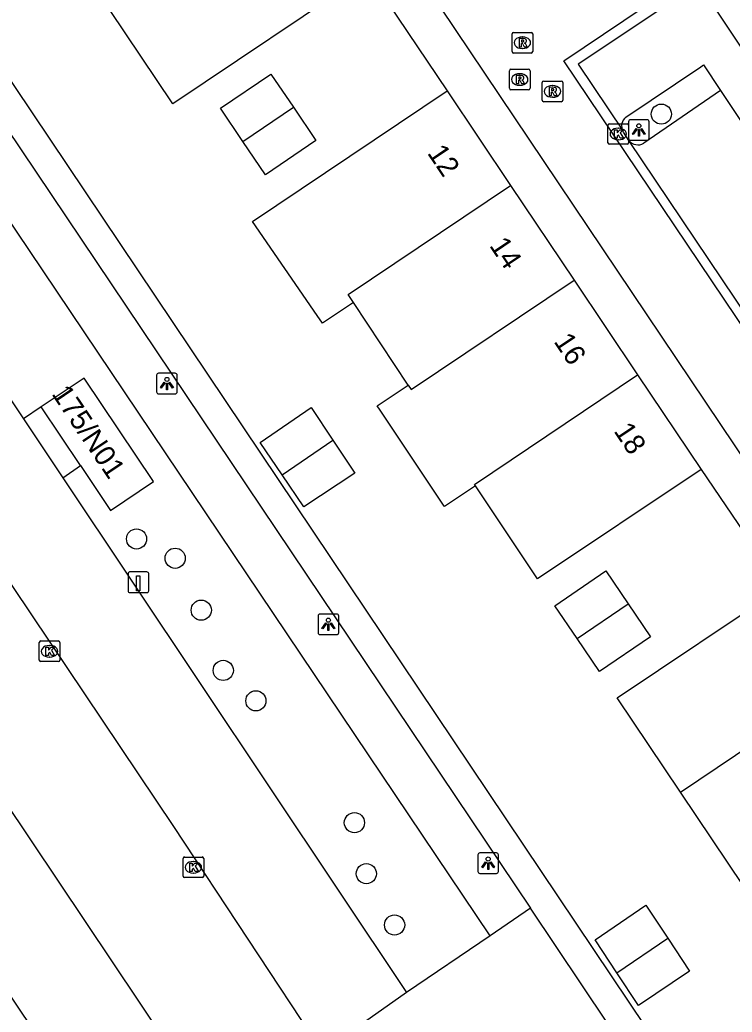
# Model space of a CAD drawing. Extents: x 158797 to 159887, y 384318 to 385255.
# Drawn here: x 159107.09 to 159141.62, y 384481.11 to 384529.23 of the extents above; entities that cross this region are included whole.
import ezdxf

# ---------------------------------------------------------------- set-up
doc = ezdxf.new("R2010")
doc.units = 0
for name, color, linetype in [('IMGEO_Boom', 7, 'Continuous'), ('IMGEO_Groenvoorziening', 7, 'Continuous'), ('IMGEO_Kolk', 7, 'Continuous'), ('IMGEO_Laadpaal', 7, 'Continuous'), ('IMGEO_Lichtpunt', 7, 'Continuous'), ('IMGEO_Pand', 7, 'Continuous'), ('IMGEO_Pand_nummerreeks', 7, 'Continuous'), ('IMGEO_Parkeervlak_open', 7, 'Continuous'), ('IMGEO_Rijbaan_lokaal_open', 7, 'Continuous'), ('IMGEO_Rioolput', 7, 'Continuous'), ('IMGEO_Voetpad_open', 7, 'Continuous')]:
    doc.layers.add(name, color=color, linetype=linetype)

msp = doc.modelspace()

# ---------------------------------------------------------------- linework, layer by layer
at = {"layer": 'IMGEO_Boom'}
for centre in [(159138.19, 384524.66), (159112.752, 384504.056), (159114.623, 384503.12), (159115.887, 384500.603), (159116.955, 384497.682), (159118.536, 384496.206), (159123.312, 384490.297), (159123.889, 384487.824), (159125.259, 384485.335)]:
    msp.add_circle(centre, 0.489, dxfattribs=at)
at = {"layer": 'IMGEO_Groenvoorziening'}
msp.add_lwpolyline([(159129.89, 384484.816), (159089.196, 384545.377)], dxfattribs=at)
at = {"layer": 'IMGEO_Kolk'}
for p, q in [((159135.603, 384523.27), (159135.603, 384524.122)), ((159135.678, 384524.196), (159136.53, 384524.196)), ((159136.604, 384524.122), (159136.604, 384523.27)), ((159136.091, 384523.976), (159136.116, 384523.976)), ((159136.53, 384523.196), (159135.678, 384523.196)), ((159136.114, 384523.416), (159136.089, 384523.416)), ((159108.107, 384499.108), (159108.959, 384499.108)), ((159108.032, 384498.182), (159108.032, 384499.034)), ((159108.52, 384498.888), (159108.545, 384498.888)), ((159109.033, 384499.034), (159109.033, 384498.182)), ((159108.543, 384498.328), (159108.518, 384498.328)), ((159108.959, 384498.108), (159108.107, 384498.108)), ((159115.005, 384487.706), (159115.005, 384488.558)), ((159115.08, 384488.632), (159115.932, 384488.632)), ((159116.006, 384488.558), (159116.006, 384487.706)), ((159115.493, 384488.412), (159115.518, 384488.412)), ((159115.932, 384487.632), (159115.08, 384487.632)), ((159115.516, 384487.852), (159115.491, 384487.852))]:
    msp.add_line(p, q, dxfattribs=at)
for points in [[(159135.603, 384523.27), (159135.603, 384524.122)], [(159135.678, 384524.196), (159136.53, 384524.196)], [(159136.604, 384524.122), (159136.604, 384523.27)], [(159135.924, 384523.896), (159136.047, 384523.896), (159136.047, 384523.745), (159136.177, 384523.896), (159136.341, 384523.896), (159136.195, 384523.745), (159136.348, 384523.496), (159136.196, 384523.496), (159136.111, 384523.66), (159136.047, 384523.593), (159136.047, 384523.496), (159135.924, 384523.496), (159135.924, 384523.896)], [(159136.53, 384523.196), (159135.678, 384523.196)], [(159108.107, 384499.108), (159108.959, 384499.108)], [(159108.032, 384498.182), (159108.032, 384499.034)], [(159108.353, 384498.808), (159108.476, 384498.808), (159108.476, 384498.657), (159108.606, 384498.808), (159108.77, 384498.808), (159108.624, 384498.657), (159108.777, 384498.408), (159108.625, 384498.408), (159108.54, 384498.572), (159108.476, 384498.505), (159108.476, 384498.408), (159108.353, 384498.408), (159108.353, 384498.808)], [(159109.033, 384499.034), (159109.033, 384498.182)], [(159108.959, 384498.108), (159108.107, 384498.108)], [(159115.005, 384487.706), (159115.005, 384488.558)], [(159115.08, 384488.632), (159115.932, 384488.632)], [(159116.006, 384488.558), (159116.006, 384487.706)], [(159115.326, 384488.332), (159115.449, 384488.332), (159115.449, 384488.181), (159115.579, 384488.332), (159115.743, 384488.332), (159115.597, 384488.181), (159115.75, 384487.932), (159115.598, 384487.932), (159115.513, 384488.096), (159115.449, 384488.029), (159115.449, 384487.932), (159115.326, 384487.932), (159115.326, 384488.332)], [(159115.932, 384487.632), (159115.08, 384487.632)]]:
    msp.add_lwpolyline(points, dxfattribs=at)
for centre, start, end in [((159135.68, 384524.12), 91.552, 178.448), ((159135.68, 384524.12), 91.552, 178.448), ((159136.528, 384524.12), 1.552, 88.448), ((159136.528, 384524.12), 1.552, 88.448), ((159135.68, 384523.272), 181.552, 268.448), ((159135.68, 384523.272), 181.552, 268.448), ((159136.528, 384523.272), 271.552, 358.448), ((159136.528, 384523.272), 271.552, 358.448), ((159108.109, 384499.032), 91.552, 178.448), ((159108.109, 384499.032), 91.552, 178.448), ((159108.957, 384499.032), 1.552, 88.448), ((159108.957, 384499.032), 1.552, 88.448), ((159108.109, 384498.184), 181.552, 268.448), ((159108.109, 384498.184), 181.552, 268.448), ((159108.957, 384498.184), 271.552, 358.448), ((159108.957, 384498.184), 271.552, 358.448), ((159115.082, 384488.556), 91.552, 178.448), ((159115.082, 384488.556), 91.552, 178.448), ((159115.93, 384488.556), 1.552, 88.448), ((159115.93, 384488.556), 1.552, 88.448), ((159115.082, 384487.708), 181.552, 268.448), ((159115.082, 384487.708), 181.552, 268.448), ((159115.93, 384487.708), 271.552, 358.448), ((159115.93, 384487.708), 271.552, 358.448)]:
    msp.add_arc(centre, 0.0765, start, end, dxfattribs=at)
for centre, major_axis, ratio, start_param, end_param in [((159136.09, 384523.696), (-0.387, 0.002), 0.722429, 4.712389, 7.853982), ((159136.115, 384523.696), (-0.39, 0.002), 0.717154, 1.570796, 4.712389), ((159108.519, 384498.608), (-0.387, 0.002), 0.722429, 4.712389, 7.853982), ((159108.544, 384498.608), (-0.39, 0.002), 0.717154, 1.570796, 4.712389), ((159115.492, 384488.132), (-0.387, 0.002), 0.722429, 4.712389, 7.853982), ((159115.517, 384488.132), (-0.39, 0.002), 0.717154, 1.570796, 4.712389)]:
    msp.add_ellipse(centre, major_axis=major_axis, ratio=ratio, start_param=start_param, end_param=end_param, dxfattribs=at)
at = {"layer": 'IMGEO_Laadpaal'}
for p, q in [((159113.257, 384502.457), (159112.416, 384502.457)), ((159113.257, 384502.457), (159112.416, 384502.457)), ((159112.341, 384502.373), (159112.341, 384501.532)), ((159112.341, 384502.373), (159112.341, 384501.532)), ((159113.341, 384501.541), (159113.341, 384502.382)), ((159113.341, 384501.541), (159113.341, 384502.382)), ((159112.425, 384501.457), (159113.266, 384501.457)), ((159112.425, 384501.457), (159113.266, 384501.457))]:
    msp.add_line(p, q, dxfattribs=at)
msp.add_lwpolyline([(159112.756, 384502.27), (159112.916, 384502.27), (159112.916, 384501.537), (159112.756, 384501.537), (159112.756, 384502.27)], dxfattribs=at)
for centre, start, end in [((159112.419, 384502.379), 92.4484, 184.2845), ((159112.419, 384502.379), 92.4484, 184.2845), ((159113.263, 384502.379), 2.4484, 94.2845), ((159113.263, 384502.379), 2.4484, 94.2845), ((159112.419, 384501.535), 182.4484, 274.2845), ((159112.419, 384501.535), 182.4484, 274.2845), ((159113.263, 384501.535), 272.4484, 4.2845), ((159113.263, 384501.535), 272.4484, 4.2845)]:
    msp.add_arc(centre, 0.0779, start, end, dxfattribs=at)
at = {"layer": 'IMGEO_Lichtpunt'}
for p, q in [((159136.602, 384524.293), (159136.602, 384523.486)), ((159136.602, 384524.293), (159136.602, 384523.486)), ((159137.504, 384524.388), (159136.696, 384524.388)), ((159137.504, 384524.388), (159136.696, 384524.388)), ((159137.598, 384523.486), (159137.598, 384524.293)), ((159137.598, 384523.486), (159137.598, 384524.293)), ((159136.696, 384523.392), (159137.504, 384523.392)), ((159136.696, 384523.392), (159137.504, 384523.392)), ((159114.625, 384512.091), (159113.817, 384512.091)), ((159114.625, 384512.091), (159113.817, 384512.091)), ((159113.723, 384511.996), (159113.723, 384511.189)), ((159113.723, 384511.996), (159113.723, 384511.189)), ((159114.719, 384511.189), (159114.719, 384511.996)), ((159114.719, 384511.189), (159114.719, 384511.996)), ((159113.817, 384511.095), (159114.625, 384511.095)), ((159113.817, 384511.095), (159114.625, 384511.095)), ((159121.553, 384500.319), (159121.553, 384499.512)), ((159121.553, 384500.319), (159121.553, 384499.512)), ((159122.455, 384500.414), (159121.647, 384500.414)), ((159122.455, 384500.414), (159121.647, 384500.414)), ((159122.549, 384499.512), (159122.549, 384500.319)), ((159122.549, 384499.512), (159122.549, 384500.319)), ((159121.647, 384499.418), (159122.455, 384499.418)), ((159121.647, 384499.418), (159122.455, 384499.418)), ((159129.297, 384488.738), (159129.297, 384487.931)), ((159129.297, 384488.738), (159129.297, 384487.931)), ((159130.199, 384488.833), (159129.391, 384488.833)), ((159130.199, 384488.833), (159129.391, 384488.833)), ((159130.293, 384487.931), (159130.293, 384488.738)), ((159130.293, 384487.931), (159130.293, 384488.738)), ((159129.391, 384487.837), (159130.199, 384487.837)), ((159129.391, 384487.837), (159130.199, 384487.837))]:
    msp.add_line(p, q, dxfattribs=at)
for points in [[(159136.976, 384523.957), (159137.015, 384523.929), (159136.827, 384523.667), (159136.789, 384523.694), (159136.976, 384523.957)], [(159137.078, 384523.909), (159137.125, 384523.909), (159137.125, 384523.587), (159137.078, 384523.587), (159137.078, 384523.909)], [(159137.188, 384523.929), (159137.226, 384523.956), (159137.413, 384523.694), (159137.374, 384523.666), (159137.188, 384523.929)], [(159114.097, 384511.66), (159114.136, 384511.632), (159113.948, 384511.37), (159113.91, 384511.397), (159114.097, 384511.66)], [(159114.199, 384511.612), (159114.246, 384511.612), (159114.246, 384511.29), (159114.199, 384511.29), (159114.199, 384511.612)], [(159114.309, 384511.632), (159114.347, 384511.659), (159114.534, 384511.397), (159114.495, 384511.369), (159114.309, 384511.632)], [(159121.927, 384499.983), (159121.966, 384499.955), (159121.778, 384499.693), (159121.74, 384499.72), (159121.927, 384499.983)], [(159122.029, 384499.935), (159122.076, 384499.935), (159122.076, 384499.613), (159122.029, 384499.613), (159122.029, 384499.935)], [(159122.139, 384499.955), (159122.177, 384499.982), (159122.364, 384499.72), (159122.325, 384499.692), (159122.139, 384499.955)], [(159129.671, 384488.402), (159129.71, 384488.374), (159129.522, 384488.112), (159129.484, 384488.139), (159129.671, 384488.402)], [(159129.773, 384488.354), (159129.82, 384488.354), (159129.82, 384488.032), (159129.773, 384488.032), (159129.773, 384488.354)], [(159129.883, 384488.374), (159129.921, 384488.401), (159130.108, 384488.139), (159130.069, 384488.111), (159129.883, 384488.374)]]:
    msp.add_lwpolyline(points, dxfattribs=at)
for centre in [(159137.101, 384524.091), (159114.222, 384511.794), (159122.052, 384500.117), (159129.796, 384488.536)]:
    msp.add_circle(centre, 0.0994, dxfattribs=at)
for centre, start, end in [((159136.696, 384524.293), 90, 180), ((159136.696, 384524.293), 90, 180), ((159137.504, 384524.293), 0, 90), ((159137.504, 384524.293), 0, 90), ((159136.696, 384523.486), 180, 270), ((159136.696, 384523.486), 180, 270), ((159137.504, 384523.486), 270, 0), ((159137.504, 384523.486), 270, 360), ((159113.817, 384511.996), 90, 180), ((159113.817, 384511.996), 90, 180), ((159114.625, 384511.996), 0, 90), ((159114.625, 384511.996), 0, 90), ((159113.817, 384511.189), 180, 270), ((159113.817, 384511.189), 180, 270), ((159114.625, 384511.189), 270, 0), ((159114.625, 384511.189), 270, 360), ((159121.647, 384500.319), 90, 180), ((159121.647, 384500.319), 90, 180), ((159122.455, 384500.319), 0, 90), ((159122.455, 384500.319), 0, 90), ((159121.647, 384499.512), 180, 270), ((159121.647, 384499.512), 180, 270), ((159122.455, 384499.512), 270, 0), ((159122.455, 384499.512), 270, 360), ((159129.391, 384488.738), 90, 180), ((159129.391, 384488.738), 90, 180), ((159130.199, 384488.738), 0, 90), ((159130.199, 384488.738), 0, 90), ((159129.391, 384487.931), 180, 270), ((159129.391, 384487.931), 180, 270), ((159130.199, 384487.931), 270, 0), ((159130.199, 384487.931), 270, 360)]:
    msp.add_arc(centre, 0.0946, start, end, dxfattribs=at)
at = {"layer": 'IMGEO_Pand'}
for points in [[(159126.029, 384461.936), (159121.905, 384459.166), (159071.774, 384533.799)], [(159123.956, 384531.511), (159114.509, 384525.165), (159111.442, 384529.73), (159111.219, 384530.062), (159112.722, 384531.071)], [(159117.91, 384523.327), (159116.822, 384524.941), (159119.268, 384526.601), (159120.354, 384524.991)], [(159123.26, 384515.516), (159121.762, 384514.518), (159121.501, 384514.897), (159118.368, 384519.453), (159127.802, 384525.792)], [(159127.802, 384525.792), (159130.881, 384521.199)], [(159120.354, 384524.991), (159121.441, 384523.38), (159118.994, 384521.72), (159117.91, 384523.327)], [(159117.91, 384523.327), (159120.354, 384524.991)], [(159123.26, 384515.516), (159123.001, 384515.905), (159130.881, 384521.199)], [(159130.881, 384521.199), (159133.961, 384516.607)], [(159125.922, 384511.522), (159126.067, 384511.304), (159133.961, 384516.607)], [(159133.961, 384516.607), (159137.04, 384512.015)], [(159125.922, 384511.522), (159123.26, 384515.516)], [(159110.027, 384507.615), (159111.49, 384505.432), (159113.576, 384506.843), (159110.211, 384511.86), (159108.122, 384510.457)], [(159129.183, 384506.629), (159129.133, 384506.703), (159137.04, 384512.015)], [(159137.04, 384512.015), (159140.119, 384507.423)], [(159129.183, 384506.629), (159127.677, 384505.625), (159127.631, 384505.694), (159124.565, 384510.295), (159124.416, 384510.518), (159125.922, 384511.522)], [(159110.027, 384507.615), (159108.122, 384510.457)], [(159119.812, 384507.166), (159118.745, 384508.741), (159121.221, 384510.427), (159122.273, 384508.841)], [(159122.273, 384508.841), (159123.325, 384507.255), (159120.863, 384505.615), (159119.812, 384507.166)], [(159119.812, 384507.166), (159122.273, 384508.841)], [(159140.119, 384507.423), (159132.189, 384502.119), (159129.183, 384506.629)], [(159134.111, 384499.224), (159133.034, 384500.821), (159135.504, 384502.503), (159136.581, 384500.905)], [(159139.121, 384491.775), (159136.05, 384496.35), (159144.008, 384501.688)], [(159136.581, 384500.905), (159137.658, 384499.307), (159135.188, 384497.625), (159134.111, 384499.224)], [(159134.111, 384499.224), (159136.581, 384500.905)], [(159139.121, 384491.775), (159147.07, 384497.12)], [(159142.186, 384487.209), (159139.121, 384491.775)], [(159136.036, 384483.019), (159134.977, 384484.616), (159137.439, 384486.292), (159138.5, 384484.696)], [(159138.5, 384484.696), (159139.56, 384483.1), (159137.088, 384481.434), (159136.036, 384483.019)], [(159136.036, 384483.019), (159138.5, 384484.696)]]:
    msp.add_lwpolyline(points, dxfattribs=at)
at = {"layer": 'IMGEO_Parkeervlak_open'}
for points in [[(159085.318, 384542.737), (159107.263, 384509.883)], [(159141.058, 384525.803), (159137.334, 384523.246)], [(159109.176, 384507.019), (159125.843, 384482.068)]]:
    msp.add_lwpolyline(points, dxfattribs=at)
msp.add_arc((159137.049, 384523.731), 0.562, 218.3312, 300.4486, dxfattribs=at)
at = {"layer": 'IMGEO_Rijbaan_lokaal_open'}
for points in [[(159108.917, 384557.49), (159163.183, 384476.655)], [(159190.205, 384527.153), (159192.762, 384528.848), (159193.039, 384528.419), (159151.428, 384500.515), (159133.468, 384527.238), (159175.064, 384555.242), (159175.35, 384554.823), (159172.804, 384553.09)], [(159125.843, 384482.068), (159121.763, 384479.19), (159114.556, 384490.118), (159081.78, 384538.994), (159081.166, 384539.91)], [(159076.06, 384536.619), (159126.029, 384461.936)], [(159140.006, 384531.001), (159134.158, 384527.09), (159136.335, 384523.829)], [(159136.608, 384523.382), (159136.361, 384523.789), (159136.347, 384523.809), (159136.335, 384523.829)], [(159143.075, 384513.765), (159136.608, 384523.382)], [(159131.847, 384486.145), (159129.89, 384484.816)], [(159146.803, 384466.42), (159146.046, 384465.91), (159145.592, 384465.604), (159131.847, 384486.145)], [(159129.89, 384484.816), (159125.843, 384482.068)]]:
    msp.add_lwpolyline(points, dxfattribs=at)
at = {"layer": 'IMGEO_Rioolput'}
for p, q in [((159130.953, 384527.697), (159130.953, 384528.549)), ((159131.028, 384528.623), (159131.88, 384528.623)), ((159131.954, 384528.549), (159131.954, 384527.697)), ((159131.441, 384528.403), (159131.466, 384528.403)), ((159131.88, 384527.623), (159131.028, 384527.623)), ((159131.464, 384527.843), (159131.439, 384527.843)), ((159130.823, 384525.912), (159130.823, 384526.764)), ((159130.898, 384526.838), (159131.75, 384526.838)), ((159131.311, 384526.618), (159131.336, 384526.618)), ((159131.824, 384526.764), (159131.824, 384525.912)), ((159131.334, 384526.058), (159131.309, 384526.058)), ((159132.412, 384525.334), (159132.412, 384526.186)), ((159132.487, 384526.26), (159133.339, 384526.26)), ((159132.9, 384526.04), (159132.925, 384526.04)), ((159133.413, 384526.186), (159133.413, 384525.334)), ((159131.75, 384525.838), (159130.898, 384525.838)), ((159133.339, 384525.26), (159132.487, 384525.26)), ((159132.923, 384525.48), (159132.898, 384525.48))]:
    msp.add_line(p, q, dxfattribs=at)
for points in [[(159130.953, 384527.697), (159130.953, 384528.549)], [(159131.028, 384528.623), (159131.88, 384528.623)], [(159131.954, 384528.549), (159131.954, 384527.697)], [(159131.542, 384528.321), (159131.29, 384528.323), (159131.29, 384527.923)], [(159131.29, 384527.923), (159131.414, 384527.923), (159131.414, 384528.085), (159131.425, 384528.085)], [(159131.468, 384528.242), (159131.414, 384528.242), (159131.414, 384528.161)], [(159131.414, 384528.161), (159131.466, 384528.161)], [(159131.472, 384528.056), (159131.543, 384527.923), (159131.683, 384527.923), (159131.618, 384528.049)], [(159131.88, 384527.623), (159131.028, 384527.623)], [(159130.823, 384525.912), (159130.823, 384526.764)], [(159130.898, 384526.838), (159131.75, 384526.838)], [(159131.412, 384526.536), (159131.16, 384526.538), (159131.16, 384526.138)], [(159131.824, 384526.764), (159131.824, 384525.912)], [(159131.16, 384526.138), (159131.284, 384526.138), (159131.284, 384526.3), (159131.295, 384526.3)], [(159131.338, 384526.457), (159131.284, 384526.457), (159131.284, 384526.376)], [(159131.284, 384526.376), (159131.336, 384526.376)], [(159131.342, 384526.271), (159131.413, 384526.138), (159131.553, 384526.138), (159131.488, 384526.264)], [(159132.412, 384525.334), (159132.412, 384526.186)], [(159132.487, 384526.26), (159133.339, 384526.26)], [(159133.413, 384526.186), (159133.413, 384525.334)], [(159131.75, 384525.838), (159130.898, 384525.838)], [(159133.001, 384525.958), (159132.749, 384525.96), (159132.749, 384525.56)], [(159132.749, 384525.56), (159132.873, 384525.56), (159132.873, 384525.722), (159132.884, 384525.722)], [(159132.927, 384525.879), (159132.873, 384525.879), (159132.873, 384525.798)], [(159132.873, 384525.798), (159132.925, 384525.798)], [(159132.931, 384525.693), (159133.002, 384525.56), (159133.142, 384525.56), (159133.077, 384525.686)], [(159133.339, 384525.26), (159132.487, 384525.26)]]:
    msp.add_lwpolyline(points, dxfattribs=at)
for centre, radius, start, end in [((159131.03, 384528.547), 0.0765, 91.552, 178.448), ((159131.03, 384528.547), 0.0765, 91.552, 178.448), ((159131.878, 384528.547), 0.0765, 1.552, 88.448), ((159131.878, 384528.547), 0.0765, 1.552, 88.448), ((159131.424, 384528.032), 0.0533, 26.0293, 88.6989), ((159131.45, 384528.35), 0.19, 274.7715, 282.9687), ((159131.474, 384528.146), 0.0964, 77.0061, 93.1865), ((159131.488, 384528.203), 0.0378, 276.6634, 79.6772), ((159131.541, 384528.211), 0.109, 350.3612, 89.416), ((159131.539, 384528.211), 0.112, 277.5842, 350.9817), ((159131.523, 384527.996), 0.108, 29.5134, 73.7905), ((159131.03, 384527.699), 0.0765, 181.552, 268.448), ((159131.03, 384527.699), 0.0765, 181.552, 268.448), ((159131.878, 384527.699), 0.0765, 271.552, 358.448), ((159131.878, 384527.699), 0.0765, 271.552, 358.448), ((159130.9, 384526.762), 0.0765, 91.552, 178.448), ((159130.9, 384526.762), 0.0765, 91.552, 178.448), ((159131.411, 384526.426), 0.109, 350.3612, 89.416), ((159131.748, 384526.762), 0.0765, 1.552, 88.448), ((159131.748, 384526.762), 0.0765, 1.552, 88.448), ((159131.294, 384526.247), 0.0533, 26.0293, 88.6989), ((159131.32, 384526.565), 0.19, 274.7715, 282.9687), ((159131.344, 384526.361), 0.0964, 77.0061, 93.1865), ((159131.358, 384526.418), 0.0378, 276.6634, 79.6772), ((159131.409, 384526.426), 0.112, 277.5842, 350.9817), ((159131.393, 384526.211), 0.108, 29.5134, 73.7905), ((159132.489, 384526.184), 0.0765, 91.552, 178.448), ((159132.489, 384526.184), 0.0765, 91.552, 178.448), ((159133.337, 384526.184), 0.0765, 1.552, 88.448), ((159133.337, 384526.184), 0.0765, 1.552, 88.448), ((159130.9, 384525.914), 0.0765, 181.552, 268.448), ((159130.9, 384525.914), 0.0765, 181.552, 268.448), ((159131.748, 384525.914), 0.0765, 271.552, 358.448), ((159131.748, 384525.914), 0.0765, 271.552, 358.448), ((159132.883, 384525.669), 0.0533, 26.0293, 88.6989), ((159132.909, 384525.987), 0.19, 274.7715, 282.9687), ((159132.933, 384525.783), 0.0964, 77.0061, 93.1865), ((159132.947, 384525.84), 0.0378, 276.6634, 79.6772), ((159133, 384525.848), 0.109, 350.3612, 89.416), ((159132.998, 384525.848), 0.112, 277.5842, 350.9817), ((159132.982, 384525.633), 0.108, 29.5134, 73.7905), ((159132.489, 384525.336), 0.0765, 181.552, 268.448), ((159132.489, 384525.336), 0.0765, 181.552, 268.448), ((159133.337, 384525.336), 0.0765, 271.552, 358.448), ((159133.337, 384525.336), 0.0765, 271.552, 358.448)]:
    msp.add_arc(centre, radius, start, end, dxfattribs=at)
for centre, major_axis, ratio, start_param, end_param in [((159131.44, 384528.123), (-0.387, 0.002), 0.722429, 4.712389, 7.853982), ((159131.465, 384528.123), (-0.39, 0.002), 0.717154, 1.570796, 4.712389), ((159131.31, 384526.338), (-0.387, 0.002), 0.722429, 4.712389, 7.853982), ((159131.335, 384526.338), (-0.39, 0.002), 0.717154, 1.570796, 4.712389), ((159132.899, 384525.76), (-0.387, 0.002), 0.722429, 4.712389, 7.853982), ((159132.924, 384525.76), (-0.39, 0.002), 0.717154, 1.570796, 4.712389)]:
    msp.add_ellipse(centre, major_axis=major_axis, ratio=ratio, start_param=start_param, end_param=end_param, dxfattribs=at)
at = {"layer": 'IMGEO_Voetpad_open'}
for points in [[(159146.803, 384466.42), (159092.403, 384547.537), (159106.711, 384557.186), (159108.605, 384554.36)], [(159089.196, 384545.377), (159091.171, 384546.721), (159131.847, 384486.145)], [(159123.956, 384531.511), (159127.802, 384525.792)], [(159143.371, 384525.955), (159140.006, 384531.001)], [(159136.474, 384524.51), (159140.1, 384526.959), (159140.226, 384527.044), (159141.058, 384525.803)], [(159141.058, 384525.803), (159146.94, 384516.973)], [(159108.122, 384510.457), (159107.263, 384509.883)], [(159107.263, 384509.883), (159109.176, 384507.019)], [(159109.176, 384507.019), (159110.027, 384507.615)], [(159140.119, 384507.423), (159144.008, 384501.688)]]:
    msp.add_lwpolyline(points, dxfattribs=at)
msp.add_arc((159136.78, 384524.093), 0.518, 126.2904, 210.6371, dxfattribs=at)

# ---------------------------------------------------------------- texts
at = {"layer": 'IMGEO_Pand_nummerreeks'}
for s, rotation, p in [('12', 303.8387, (159126.817, 384522.772)), ('14', 303.8501, (159129.828, 384518.283)), ('16', 303.8444, (159132.945, 384513.634)), ('175/N01', 303.8387, (159108.609, 384511.093)), ('18', 303.8444, (159135.856, 384509.293))]:
    msp.add_text(s, height=1, rotation=rotation, dxfattribs=at).set_placement(p)

doc.saveas('drawing.dxf')
